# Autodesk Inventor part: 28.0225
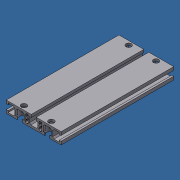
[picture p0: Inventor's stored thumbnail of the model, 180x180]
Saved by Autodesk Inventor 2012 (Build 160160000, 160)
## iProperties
Created: 2007-06
Part Number: 28.0225
Material: Aluminum-6061
Document SubType Name: Modeling
Designer: Andy Moles
Density: 2.71 g/cm^3
Mass: 360.485 g
Surface Area: 895.823 cm^2
Volume: 133.02 cm^3
Stock Number: 20.0995 PROFILE 90X19
Vendor: F
Description: L = 7.283", MILL TO 28.0225
Author: Andy Moles
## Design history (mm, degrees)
sketch "Sketch1"
  geometry: L1 (18.4, -9.5)-(18.4, -5) reference; L2 (17.9, -5)-(15.7, -5) reference; L3 (15.7, -5)-(15.7, 3.5) reference; L4 (15.7, 3.5)-(18, 5.8) reference; L5 (18, 5.8)-(27, 5.8) reference; L6 (27, 5.8)-(29.3, 3.5) reference; L7 (29.3, 3.5)-(29.3, -5) reference; L8 (26.6, -5)-(26.6, -9.5) reference; L9 (45, -9.5)-(26.9, -9.5) reference; L10 (45, -4.1)-(45, -9.5) reference; L11 (45, -4.1)-(42, -4.1) reference; L12 (42, -4.6)-(42, -6.8) reference; L13 (42, -6.8)-(33.5, -6.8) reference; L14 (33.5, -6.8)-(31.2, -4.5) reference; L15 (31.2, -4.5)-(31.2, 4.5) reference; L16 (31.2, 4.5)-(33.5, 6.8) reference; L17 (33.5, 6.8)-(42, 6.8) reference; L18 (42, 4.1)-(45, 4.1) reference; L19 (45, 9.5)-(45, 4.1) reference; L20 (4.4, 9.5)-(45, 9.5) reference; L21 (4.1, 9.5)-(4.1, 5) reference; L22 (4.6, 5)-(6.8, 5) reference; L23 (6.8, 5)-(6.8, -3.5) reference; L24 (6.8, -3.5)-(4.5, -5.8) reference; L25 (4.5, -5.8)-(-4.5, -5.8) reference; L26 (-4.5, -5.8)-(-6.8, -3.5) reference; L27 (-6.8, -3.5)-(-6.8, 5) reference; L28 (-4.1, 5)-(-4.1, 9.5) reference; L29 (-45, 4.1)-(-45, 9.5) reference; L30 (-45, 4.1)-(-42, 4.1) reference; L31 (-42, 4.1)-(-42, 6.8) reference; L32 (-42, 6.8)-(-33.5, 6.8) reference; L33 (-33.5, 6.8)-(-31.2, 4.5) reference; L34 (-31.2, 4.5)-(-31.2, -4.5) reference; L35 (-31.2, -4.5)-(-33.5, -6.8) reference; L36 (-33.5, -6.8)-(-42, -6.8) reference; L37 (-42, -6.8)-(-42, -4.1) reference; L38 (-42, -4.1)-(-45, -4.1) reference; L39 (-45, -9.5)-(-45, -4.1) reference; L40 (-26.6, -9.5)-(-26.6, -5) reference; L41 (-29.3, -5)-(-29.3, 3.5) reference; L42 (-29.3, 3.5)-(-27, 5.8) reference; L43 (-27, 5.8)-(-18, 5.8) reference; L44 (-18, 5.8)-(-15.7, 3.5) reference; L45 (-15.7, 3.5)-(-15.7, -5) reference; L46 (-15.7, -5)-(-17.9, -5) reference; L47 (-18.4, -5)-(-18.4, -9.5) reference; L48 (-18.1, -9.5)-(-18.4, -9.5) reference; L49 (-26.6, -9.5)-(-45, -9.5) reference; L50 (-17.9, -5)-(-18.4, -5) reference; L51 (-26.6, -5)-(-29.3, -5) reference; L52 (-6.8, 5)-(-4.1, 5) reference; L53 (4.1, 5)-(4.6, 5) reference; L54 (-45, 9.5)-(-4.1, 9.5) reference; L55 (4.1, 9.5)-(4.4, 9.5) reference; L56 (29.3, -5)-(26.6, -5) reference; L57 (18.4, -5)-(17.9, -5) reference; L58 (26.9, -9.5)-(26.6, -9.5) reference; L59 (18.4, -9.5)-(-18.1, -9.5) reference; L60 (42, 6.8)-(42, 4.1) reference; L61 (42, -4.1)-(42, -4.6) reference; L62 (13.3, 5)-(13.3, 3.657); L63 (13.007, 2.95)-(12.646, 2.59); L64 (10.7, 7)-(11.3, 7)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; A1 r 1 centre (12.3, 3.657) between (13.007, 2.95) and (13.3, 3.657); A2 r 0.5 centre (13, 2.236) between (12.646, 2.59) and (12.667, 1.863); A3 r 2 centre (11.3, 5) between (13.3, 5) and (11.3, 7); A4 r 0.5 centre (9, 2.236) between (9.333, 1.863) and (9.354, 2.59); A5 r 1 centre (9.7, 3.657) between (8.7, 3.657) and (8.993, 2.95); A6 r 2 centre (10.7, 5) between (10.7, 7) and (8.7, 5); A7 r 1 centre (9.7, -3.657) between (8.993, -2.95) and (8.7, -3.657); A8 r 2.5 centre (11, 0) between (9.333, 1.863) and (9.333, -1.863); A9 r 0.5 centre (9, -2.236) between (9.354, -2.59) and (9.333, -1.863); A10 r 2 centre (10.7, -5) between (8.7, -5) and (10.7, -7); A11 r 2.5 centre (11, 0) between (12.667, -1.863) and (12.667, 1.863); A12 r 0.5 centre (13, -2.236) between (12.667, -1.863) and (12.646, -2.59); A13 r 1 centre (12.3, -3.657) between (13.3, -3.657) and (13.007, -2.95); A14 r 2 centre (11.3, -5) between (11.3, -7) and (13.3, -5); A15 r 2.5 centre (-11, 0) between (-9.333, -1.863) and (-9.333, 1.863); A16 r 1 centre (-9.7, -3.657) between (-8.7, -3.657) and (-8.993, -2.95); A17 r 2 centre (-10.7, -5) between (-10.7, -7) and (-8.7, -5); A18 r 0.5 centre (-9, -2.236) between (-9.333, -1.863) and (-9.354, -2.59); A19 r 1 centre (-12.3, -3.657) between (-13.007, -2.95) and (-13.3, -3.657); A20 r 2.5 centre (-11, 0) between (-12.667, 1.863) and (-12.667, -1.863); A21 r 2 centre (-11.3, -5) between (-13.3, -5) and (-11.3, -7); A22 r 0.5 centre (-13, -2.236) between (-12.646, -2.59) and (-12.667, -1.863); A23 r 0.5 centre (-13, 2.236) between (-12.667, 1.863) and (-12.646, 2.59); A24 r 2 centre (-11.3, 5) between (-11.3, 7) and (-13.3, 5); A25 r 0.5 centre (-9, 2.236) between (-9.354, 2.59) and (-9.333, 1.863); A26 r 1 centre (-9.7, 3.657) between (-8.993, 2.95) and (-8.7, 3.657); A27 r 2 centre (-10.7, 5) between (-8.7, 5) and (-10.7, 7); A28 r 1 centre (-12.3, 3.657) between (-13.3, 3.657) and (-13.007, 2.95)
  constraints: 162 end point, 56 point on circle, 28 centre point, 28 horizontal, 23 vertical, 71 other
extrude "Extrusion1" new body sketch "Sketch1" stored distance "d0" = 185; taper "d1" = 0 deg
sketch "Sketch2"
  geometry: L1 (0, -185)-(36.8, -185) reference; L2 (63.4, -185)-(63.4, 0) reference; 6 further points
  constraints: 2 horizontal alignment, 2 vertical alignment
  dimensions: "d2" = 185 distance of L1.end point (36.8, 0) (derived); "d3" = 172 distance of point (40.9, -178.5) point (40.9, -6.5); "d4" = 6.5 distance from line of point (40.9, -178.5) L1 (= -0.5 x d3 + 0.5 x d2); "d5" = 22.5 distance from line of point (40.9, -6.5) L2; "d6" = 67.5 distance from line of point (-4.1, -6.5) L2
hole "Hole1" sketch "Sketch2" at (40.9, -6.5), (-4.1, -6.5), (-4.1, -178.5), (40.9, -178.5) diameter "d7" = 9; stored, may be unused: countersink angle "d11" = 90 deg, drill point angle "d13" = 118 deg; dims "d8" = 6, "d9" = 15, "d10" = 15.3, "d12" = 8
body "Solid1"
